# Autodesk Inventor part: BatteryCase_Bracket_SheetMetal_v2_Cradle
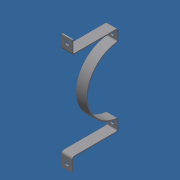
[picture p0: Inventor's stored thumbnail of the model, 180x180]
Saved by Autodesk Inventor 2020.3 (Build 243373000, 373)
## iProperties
Created: 2020-09
Part Number: BatteryCase_Bracket_SheetMetal_v2_Cradle
Material: Generic
Document SubType Name: Sheet Metal
Designer: biggshj
Manufacturer: Standard
Standards Organization: Custom
Density: 1 g/cm^3
Sheet Metal Rule: Default_mm
Appearance: Default
Mass: 66.4177 g
Surface Area: 483.3 cm^2
Volume: 66.4177 cm^3
Author: biggshj
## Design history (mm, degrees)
node "Contour Flange1"
  sketch "Sketch2"
    geometry: L1 (0, 77.84)-(0, 107.84); L2 (0, 107.84)-(-108, 107.84); L3 (-108, 107.84)-(-108, 137.84); L4 (0, -77.84)-(0, -107.84); L5 (0, -107.84)-(-108, -107.84); L6 (-108, -107.84)-(-108, -137.84); L7 (0, 0)-(5, 0); L8 (0, -192.975)-(0, 192.975) reference; A1 r 78 centre (5, 0) between (0, 77.84) and (0, -77.84)
    constraints: 14 end point, 4 perpendicular, 2 collinear, 2 point on circle, 2 vertical, 1 centre point, 1 coincident, 1 horizontal
    dimensions: "d0" = 5 distance of L7.start L7.end; "d1" = 78 radius of A1; "d2" = 30 distance of L4.start L4.end; "d3" = 108 distance of L4.end L5.end; "d4" = 30 distance of L5.end L6.end; "d5" = 30 distance of L1.start L1.end; "d6" = 108 distance of L1.end L2.end; "d7" = 30 distance of L2.end L3.end
sketch "Sketch3"
  geometry: L1 (0, 0)-(0, 13.5); L2 (0, 27)-(0, 0) reference; L3 (0, 137.84)-(0, 12.84); L4 (0, 12.84)-(12.5, 12.84); C1 r 5 at (12.5, 12.84)
  constraints: 6 end point, 1 centre point, 1 coincident, 1 horizontal, 1 midpoint, 1 point on line
  dimensions: "d33" = 125 distance of L3.start L3.end; "d34" = 10 diameter of C1; "d35" = 12.5 distance of L3.end L4.end
extrude "Extrusion1" cut sketch "Sketch3" distance "d23" = 10; taper "d24" = 0 deg
mirror "Mirror1"
sketch "Sketch4"
  geometry: L1 (0, 101.84)-(0, 9.84); L2 (0, 9.84)-(12.5, 9.84); C1 r 5 at (12.5, 9.84)
  constraints: 4 end point, 1 centre point, 1 coincident, 1 horizontal, 1 vertical
  dimensions: "d25" = 92 distance of L1.start L1.end; "d26" = 12.5 distance of L1.end L2.end; "d28" = 10 diameter of C1
extrude "Extrusion2" cut sketch "Sketch4" distance "d30" = 10; taper "d31" = 0 deg
mirror "Mirror2"
body "Solid1"
face "Plate1" dims "d8" = 3 (= Thickness), "d9" = 3 (= BendReliefWidth), "d10" = 1.5 (= BendReliefDepth), "d11" = 6 (= MinimumRemnant), "d12" = 3 (= TransitionRadius), "d13" = 25, "d14" = 3 (= BendRadius), "d15" = 3.048, "d16" = 12 (= CornerReliefSize), "d17" = 3 (= GapSize), "d18" = 3 (= JacobiRadiusSize), "SeamGap" = 0.01
bend "Bend1" dims "d8" = 3 (= Thickness), "d9" = 3 (= BendReliefWidth), "d10" = 1.5 (= BendReliefDepth), "d11" = 6 (= MinimumRemnant), "d12" = 3 (= TransitionRadius), "d14" = 3 (= BendRadius), "d15" = 3.048, "SeamGap" = 0.01
feature "Corner1" dims "d15" = 3.048, "d16" = 12 (= CornerReliefSize), "d17" = 3 (= GapSize), "d18" = 3 (= JacobiRadiusSize)
other parameters: "Thickness" = 3 (derived), "BendRadius" = 3 (= Thickness), "BendReliefWidth" = 3 (= Thickness), "BendReliefDepth" = 1.5 (= 0.5 x Thickness), "CornerReliefSize" = 12 (= 4 x Thickness), "MinimumRemnant" = 6 (= 2 x Thickness), "TransitionRadius" = 3 (= BendRadius), "JacobiRadiusSize" = 3 (= BendRadius), "GapSize" = 3 (= Thickness)
